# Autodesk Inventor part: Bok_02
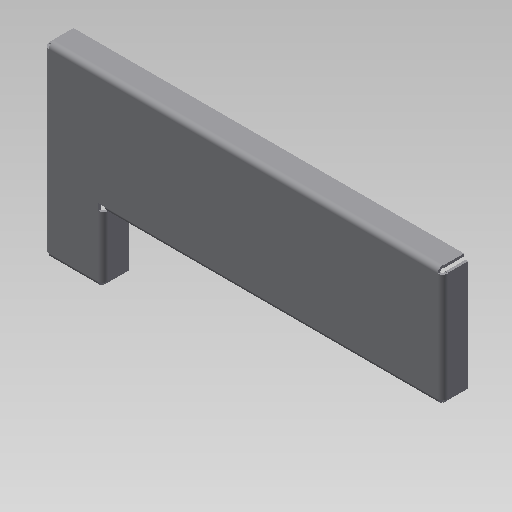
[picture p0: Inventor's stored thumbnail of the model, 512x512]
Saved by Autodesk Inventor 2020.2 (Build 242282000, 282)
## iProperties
Created: 2014-09
Part Number: Bok_02
Material: Ogólny
Document SubType Name: Konstrukcja blachowa
Designer: F.Stasiak
Density: 1 g/cm^3
Sheet Metal Rule: Domyślny
Appearance: Domyślna
Catalog Web Link: www.expertbooks.pl
Manager: www.cadconsulting.pl
Company: Fabian Stasiak CAD Consulting
Author: F.Stasiak
Subject: Zbiór ćwiczeń. Autodesk Inventor 2020. Kurs Professional
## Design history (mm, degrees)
derived "Bok_01.ipt"
  sketch "Szkic1"
    geometry: L1 (200, -40)-(200, 0) reference; L2 (200, 0)-(0, 0) reference; L3 (0, 0)-(0, 70) reference; L4 (0, 70)-(235, 70) reference; L5 (235, 70)-(235, -40) reference; L6 (235, -40)-(200, -40) reference; 1 further point
  sketch "Szkic2"
    geometry: L1 (0, 15)-(110, 15) reference; L2 (110, 15)-(110, 0) reference; 1 other entity
    constraints: 2 other
feature "Bryła1::Bok_01.ipt" dims "d0" = 10
tag "Bryła wyprowadzona1"
node "Bryła1"
other parameters: "Grubość" = 0.5, "WspółczynnikK" = 4.4, "PromieńGięcia" = 0.5 (= Grubość), "SzerokośćGięciaPodcięcia" = 0.5 (= Grubość), "GłębokośćGięciaPodcięcia" = 0.25 (= 0.5 x Grubość), "RozmiarPodcięciaNarożnika" = 2 (= 4 x Grubość), "OdstępPołączenia" = 0.01, "MinimalnaPozostałość" = 1 (= 2 x Grubość), "PromieńPrzejścia" = 0.5 (= PromieńGięcia), "Rozmiar_promienia_Jacobiego" = 0.5 (= Grubość), "Wielk_odstępu" = 0.5 (= Grubość)
